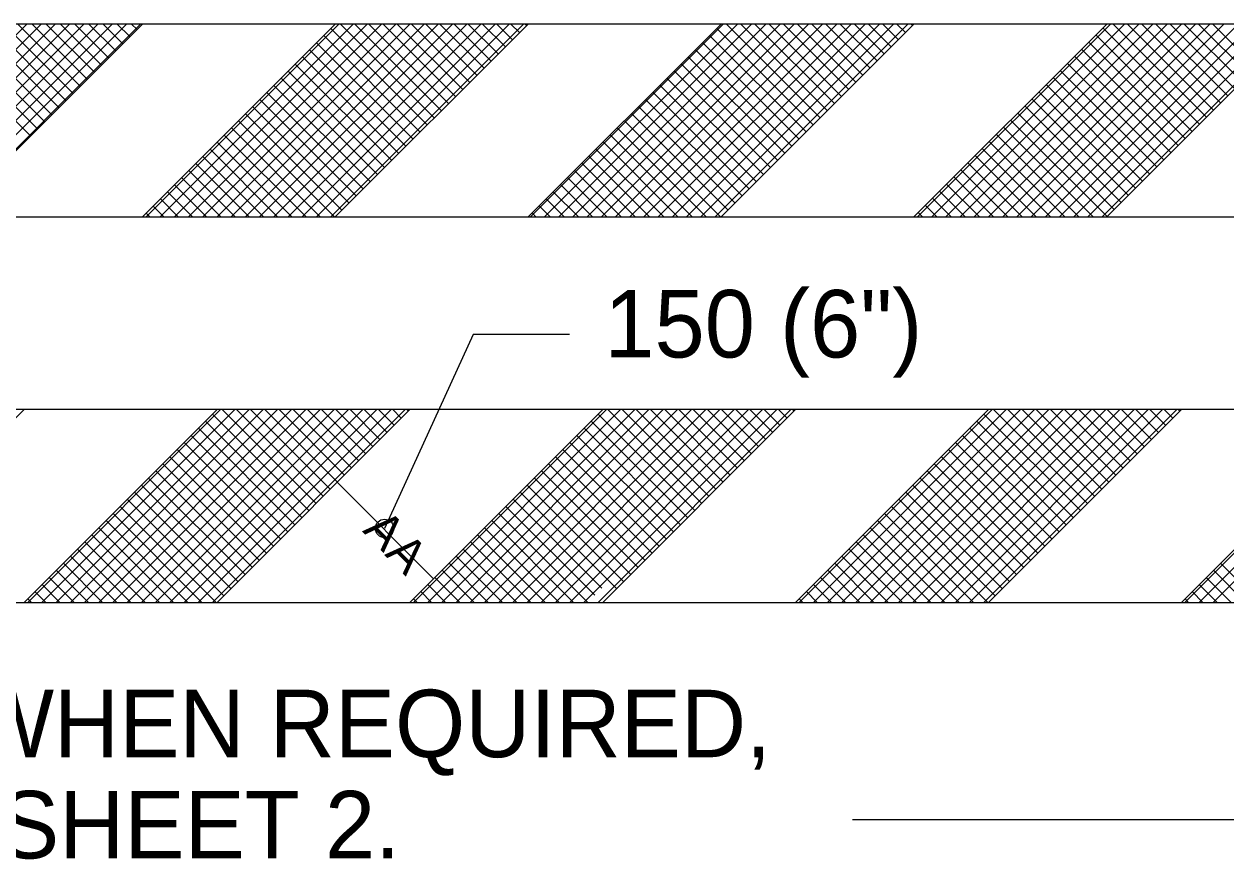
# Model space of a CAD drawing. Extents: x -4 to 901, y -468 to 720.
# Drawn here: x 457.6 to 517.4, y 595.4 to 637.6 of the extents above; entities that cross this region are included whole.
import ezdxf

# ---------------------------------------------------------------- set-up
doc = ezdxf.new("R2010")
doc.units = 0
doc.layers.add('2', color=7, linetype='Continuous')
doc.layers.add('3', color=7, linetype='Continuous')

msp = doc.modelspace()

# ---------------------------------------------------------------- linework, layer by layer
at = {"layer": '2'}
for p, q in [((453.8525, 627.995125), (463.4525, 637.595125)), ((463.4525, 627.995125), (473.0525, 637.595125)), ((473.0525, 627.995125), (482.6525, 637.595125)), ((482.6525, 627.995125), (492.2525, 637.595125)), ((492.2525, 627.995125), (501.8525, 637.595125)), ((501.8525, 627.995125), (511.4525, 637.595125)), ((511.4525, 627.995125), (521.0525, 637.595125)), ((447.9665, 608.795125), (457.5665, 618.395125)), ((457.5665, 608.795125), (467.1665, 618.395125)), ((457.5665, 608.795125), (467.1665, 618.395125)), ((457.5665, 608.795125), (467.1665, 618.395125)), ((457.5665, 608.795125), (467.1665, 618.395125)), ((457.5665, 608.795125), (467.1665, 618.395125)), ((462.7045, 613.933125), (467.1665, 618.395125)), ((467.1665, 608.795125), (476.7665, 618.395125)), ((476.7665, 608.795125), (486.3665, 618.395125)), ((476.7665, 608.795125), (486.3665, 618.395125)), ((476.7665, 608.795125), (486.3665, 618.395125)), ((476.7665, 608.795125), (486.3665, 618.395125)), ((476.7665, 608.795125), (486.3665, 618.395125)), ((476.7665, 608.795125), (486.3665, 618.395125)), ((481.9045, 613.933125), (486.3665, 618.395125)), ((486.3665, 608.795125), (495.9665, 618.395125)), ((495.9665, 608.795125), (505.5665, 618.395125)), ((495.9665, 608.795125), (505.5665, 618.395125)), ((495.9665, 608.795125), (505.5665, 618.395125)), ((495.9665, 608.795125), (505.5665, 618.395125)), ((495.9665, 608.795125), (505.5665, 618.395125)), ((495.9665, 608.795125), (505.5665, 618.395125)), ((495.9665, 608.795125), (505.5665, 618.395125)), ((501.1045, 613.933125), (505.5665, 618.395125)), ((505.5665, 608.795125), (515.1665, 618.395125)), ((515.1665, 608.795125), (524.7665, 618.395125)), ((515.1665, 608.795125), (524.7665, 618.395125)), ((515.1665, 608.795125), (524.7665, 618.395125)), ((515.1665, 608.795125), (524.7665, 618.395125)), ((515.1665, 608.795125), (524.7665, 618.395125)), ((515.1665, 608.795125), (524.7665, 618.395125)), ((515.1665, 608.795125), (524.7665, 618.395125)), ((515.1665, 608.795125), (524.7665, 618.395125)), ((477.9465, 609.975125), (473.1465, 614.775125)), ((519.64075, 597.967625), (498.79225, 597.967625))]:
    msp.add_line(p, q, dxfattribs=at)
for points in [[(405.1045, 637.595125), (405.1045, 627.995125), (536.7925, 627.995125), (536.7925, 637.595125)], [(405.1045, 618.395125), (405.1045, 608.795125), (536.7925, 608.795125), (536.7925, 618.395125)]]:
    msp.add_lwpolyline(points, close=True, dxfattribs=at)
for points in [[(448.1, 627.995125), (457.7, 637.595125)], [(448.807, 627.995125), (458.407, 637.595125)], [(449.514, 627.995125), (459.114, 637.595125)], [(450.2215, 627.995125), (459.8215, 637.595125)], [(450.9285, 627.995125), (460.5285, 637.595125)], [(451.6355, 627.995125), (461.2355, 637.595125)], [(452.3425, 627.995125), (461.9425, 637.595125)], [(453.05, 627.995125), (462.65, 637.595125)], [(453.757, 627.995125), (463.357, 637.595125)], [(458.584, 632.726625), (453.784, 637.526625)], [(458.9375, 633.080125), (454.4225, 637.595125)], [(459.291, 633.433625), (455.1295, 637.595125)], [(459.6445, 633.787125), (455.8365, 637.595125)], [(459.998, 634.140625), (456.5435, 637.595125)], [(460.35175, 634.494375), (457.251, 637.595125)], [(460.70525, 634.847875), (457.958, 637.595125)], [(461.05875, 635.201375), (458.665, 637.595125)], [(461.41225, 635.554875), (459.372, 637.595125)], [(461.76575, 635.908375), (460.079, 637.595125)], [(462.1195, 636.262125), (460.7865, 637.595125)], [(462.473, 636.615625), (461.4935, 637.595125)], [(462.8265, 636.969125), (462.2005, 637.595125)], [(463.18, 637.322625), (462.9075, 637.595125)], [(463.62875, 627.995125), (473.22875, 637.595125)], [(464.33575, 627.995125), (473.93575, 637.595125)], [(465.04275, 627.995125), (474.64275, 637.595125)], [(465.74975, 627.995125), (475.34975, 637.595125)], [(466.45675, 627.995125), (476.05675, 637.595125)], [(467.16375, 627.995125), (476.76375, 637.595125)], [(467.87075, 627.995125), (477.47075, 637.595125)], [(468.57825, 627.995125), (478.17825, 637.595125)], [(469.28525, 627.995125), (478.88525, 637.595125)], [(469.99225, 627.995125), (479.59225, 637.595125)], [(470.69925, 627.995125), (480.29925, 637.595125)], [(471.40675, 627.995125), (481.00675, 637.595125)], [(472.11375, 627.995125), (481.71375, 637.595125)], [(472.82075, 627.995125), (482.42075, 637.595125)], [(477.62675, 632.569625), (472.827, 637.369375)], [(477.98025, 632.923125), (473.30825, 637.595125)], [(478.33375, 633.276625), (474.01525, 637.595125)], [(478.68725, 633.630125), (474.72225, 637.595125)], [(479.04075, 633.983625), (475.42925, 637.595125)], [(479.3945, 634.337375), (476.13675, 637.595125)], [(479.748, 634.690875), (476.84375, 637.595125)], [(480.1015, 635.044375), (477.55075, 637.595125)], [(480.455, 635.397875), (478.25775, 637.595125)], [(480.8085, 635.751375), (478.96475, 637.595125)], [(481.162, 636.104875), (479.67175, 637.595125)], [(481.5155, 636.458375), (480.37875, 637.595125)], [(481.869, 636.811875), (481.08575, 637.595125)], [(482.2225, 637.165375), (481.79275, 637.595125)], [(482.57625, 637.519125), (482.50025, 637.595125)], [(482.76, 627.995125), (492.36, 637.595125)], [(483.467, 627.995125), (493.067, 637.595125)], [(484.1745, 627.995125), (493.7745, 637.595125)], [(484.8815, 627.995125), (494.4815, 637.595125)], [(485.5885, 627.995125), (495.1885, 637.595125)], [(486.2955, 627.995125), (495.8955, 637.595125)], [(487.003, 627.995125), (496.603, 637.595125)], [(487.71, 627.995125), (497.31, 637.595125)], [(488.417, 627.995125), (498.017, 637.595125)], [(489.124, 627.995125), (498.724, 637.595125)], [(489.831, 627.995125), (499.431, 637.595125)], [(490.5385, 627.995125), (500.1385, 637.595125)], [(491.2455, 627.995125), (500.8455, 637.595125)], [(491.9525, 627.995125), (501.5525, 637.595125)], [(496.8355, 632.578125), (492.0355, 637.378125)], [(497.189, 632.931625), (492.5255, 637.595125)], [(497.5425, 633.285125), (493.2325, 637.595125)], [(497.896, 633.638625), (493.9395, 637.595125)], [(498.24975, 633.992375), (494.647, 637.595125)], [(498.60325, 634.345875), (495.354, 637.595125)], [(498.95675, 634.699375), (496.061, 637.595125)], [(499.31025, 635.052875), (496.768, 637.595125)], [(499.66375, 635.406375), (497.475, 637.595125)], [(500.0175, 635.760125), (498.1825, 637.595125)], [(500.371, 636.113625), (498.8895, 637.595125)], [(500.7245, 636.467125), (499.5965, 637.595125)], [(501.078, 636.820625), (500.3035, 637.595125)], [(501.43175, 637.174375), (501.011, 637.595125)], [(501.78525, 637.527875), (501.718, 637.595125)], [(502.032, 627.995125), (511.632, 637.595125)], [(502.739, 627.995125), (512.339, 637.595125)], [(503.4465, 627.995125), (513.0465, 637.595125)], [(504.1535, 627.995125), (513.7535, 637.595125)], [(504.8605, 627.995125), (514.4605, 637.595125)], [(505.5675, 627.995125), (515.1675, 637.595125)], [(506.275, 627.995125), (515.875, 637.595125)], [(506.982, 627.995125), (516.582, 637.595125)], [(507.689, 627.995125), (517.289, 637.595125)], [(508.396, 627.995125), (517.996, 637.595125)], [(509.103, 627.995125), (518.703, 637.595125)], [(509.8105, 627.995125), (519.4105, 637.595125)], [(510.5175, 627.995125), (520.1175, 637.595125)], [(511.2245, 627.995125), (520.8245, 637.595125)], [(516.06225, 632.605125), (511.26225, 637.405125)], [(516.41575, 632.958625), (511.77925, 637.595125)], [(516.76925, 633.312125), (512.48625, 637.595125)], [(517.12275, 633.665625), (513.19325, 637.595125)], [(517.4765, 634.019375), (513.90075, 637.595125)], [(517.83, 634.372875), (514.60775, 637.595125)], [(518.1835, 634.726375), (515.31475, 637.595125)], [(518.537, 635.079875), (516.02175, 637.595125)], [(518.8905, 635.433375), (516.72875, 637.595125)], [(457.87675, 632.019375), (453.07675, 636.819375)], [(458.23025, 632.372875), (453.43025, 637.172875)], [(476.9195, 631.861875), (472.1195, 636.661875)], [(477.27325, 632.215625), (472.47325, 637.015625)], [(496.12825, 631.870875), (491.32825, 636.670875)], [(496.482, 632.224625), (491.682, 637.024625)], [(515.355, 631.897875), (510.555, 636.697875)], [(515.70875, 632.251625), (510.90875, 637.051625)], [(476.566, 631.508375), (471.766, 636.308375)], [(495.77475, 631.517375), (490.97475, 636.317375)], [(515.0015, 631.544375), (510.2015, 636.344375)], [(475.859, 630.801375), (471.059, 635.601375)], [(476.2125, 631.154875), (471.4125, 635.954875)], [(495.06775, 630.810375), (490.26775, 635.610375)], [(495.42125, 631.163875), (490.62125, 635.963875)], [(514.2945, 630.837375), (509.4945, 635.637375)], [(514.648, 631.190875), (509.848, 635.990875)], [(475.15175, 630.094125), (470.35175, 634.894125)], [(475.50525, 630.447625), (470.70525, 635.247625)], [(494.3605, 630.103125), (489.5605, 634.903125)], [(494.714, 630.456625), (489.914, 635.256625)], [(513.58725, 630.130125), (508.78725, 634.930125)], [(513.94075, 630.483625), (509.14075, 635.283625)], [(474.79825, 629.740625), (469.99825, 634.540625)], [(494.007, 629.749625), (489.207, 634.549625)], [(512.88025, 629.423125), (508.08025, 634.223125)], [(513.23375, 629.776625), (508.43375, 634.576625)], [(474.09125, 629.033625), (469.29125, 633.833625)], [(474.44475, 629.387125), (469.64475, 634.187125)], [(493.3, 629.042625), (488.5, 633.842625)], [(493.6535, 629.396125), (488.8535, 634.196125)], [(512.52675, 629.069625), (507.72675, 633.869625)], [(473.384, 628.326375), (468.584, 633.126375)], [(473.7375, 628.679875), (468.9375, 633.479875)], [(492.59275, 628.335375), (487.79275, 633.135375)], [(492.94625, 628.688875), (488.14625, 633.488875)], [(511.8195, 628.362375), (507.0195, 633.162375)], [(512.173, 628.715875), (507.373, 633.515875)], [(472.30125, 627.995125), (467.877, 632.419375)], [(473.0305, 627.972875), (468.2305, 632.772875)], [(491.519, 627.995125), (487.08575, 632.428375)], [(492.23925, 627.981875), (487.43925, 632.781875)], [(510.77275, 627.995125), (506.3125, 632.455375)], [(511.466, 628.008875), (506.666, 632.808875)], [(471.59425, 627.995125), (467.5235, 632.065875)], [(490.812, 627.995125), (486.73225, 632.074875)], [(510.06575, 627.995125), (505.959, 632.101875)], [(470.18025, 627.995125), (466.8165, 631.358875)], [(470.88725, 627.995125), (467.17, 631.712375)], [(489.3975, 627.995125), (486.025, 631.367625)], [(490.1045, 627.995125), (486.3785, 631.721125)], [(508.65125, 627.995125), (505.25175, 631.394625)], [(509.35825, 627.995125), (505.60525, 631.748125)], [(468.76625, 627.995125), (466.1095, 630.651875)], [(469.47325, 627.995125), (466.463, 631.005375)], [(487.9835, 627.995125), (485.318, 630.660625)], [(488.6905, 627.995125), (485.6715, 631.014125)], [(507.23725, 627.995125), (504.54475, 630.687625)], [(507.94425, 627.995125), (504.89825, 631.041125)], [(468.05875, 627.995125), (465.75575, 630.298125)], [(487.2765, 627.995125), (484.9645, 630.307125)], [(506.53025, 627.995125), (504.19125, 630.334125)], [(466.64475, 627.995125), (465.04875, 629.591125)], [(467.35175, 627.995125), (465.40225, 629.944625)], [(485.862, 627.995125), (484.25725, 629.599875)], [(486.569, 627.995125), (484.61075, 629.953375)], [(505.11575, 627.995125), (503.484, 629.626875)], [(505.82275, 627.995125), (503.8375, 629.980375)], [(465.23075, 627.995125), (464.34175, 628.884125)], [(465.93775, 627.995125), (464.69525, 629.237625)], [(484.448, 627.995125), (483.55025, 628.892875)], [(485.155, 627.995125), (483.90375, 629.246375)], [(503.70175, 627.995125), (502.777, 628.919875)], [(504.40875, 627.995125), (503.1305, 629.273375)], [(464.52325, 627.995125), (463.988, 628.530375)], [(483.7405, 627.995125), (483.1965, 628.539125)], [(502.99425, 627.995125), (502.42325, 628.566125)], [(463.81625, 627.995125), (463.6345, 628.176875)], [(483.0335, 627.995125), (482.843, 628.185625)], [(502.28725, 627.995125), (502.06975, 628.212625)], [(484.7145, 622.141125), (479.9145, 622.141125), (475.5025, 612.477125)], [(457.74275, 608.795125), (467.34275, 618.395125)], [(458.44975, 608.795125), (468.04975, 618.395125)], [(459.15675, 608.795125), (468.75675, 618.395125)], [(459.86375, 608.795125), (469.46375, 618.395125)], [(460.57075, 608.795125), (470.17075, 618.395125)], [(461.27775, 608.795125), (470.87775, 618.395125)], [(461.98475, 608.795125), (471.58475, 618.395125)], [(462.69225, 608.795125), (472.29225, 618.395125)], [(463.39925, 608.795125), (472.99925, 618.395125)], [(464.10625, 608.795125), (473.70625, 618.395125)], [(464.81325, 608.795125), (474.41325, 618.395125)], [(465.52075, 608.795125), (475.12075, 618.395125)], [(466.22775, 608.795125), (475.82775, 618.395125)], [(466.93475, 608.795125), (476.53475, 618.395125)], [(471.7405, 613.369375), (466.94075, 618.169125)], [(472.094, 613.722875), (467.42175, 618.395125)], [(472.4475, 614.076375), (468.12875, 618.395125)], [(472.801, 614.429875), (468.83575, 618.395125)], [(473.1545, 614.783375), (469.54275, 618.395125)], [(473.50825, 615.137125), (470.25025, 618.395125)], [(473.86175, 615.490625), (470.95725, 618.395125)], [(474.2155, 615.844375), (471.66475, 618.395125)], [(474.569, 616.197875), (472.37175, 618.395125)], [(474.9225, 616.551375), (473.07875, 618.395125)], [(475.276, 616.904875), (473.78575, 618.395125)], [(475.6295, 617.258375), (474.49275, 618.395125)], [(475.983, 617.611875), (475.19975, 618.395125)], [(476.3365, 617.965375), (475.90675, 618.395125)], [(476.69025, 618.319125), (476.61425, 618.395125)], [(476.94275, 608.795125), (486.54275, 618.395125)], [(477.64975, 608.795125), (487.24975, 618.395125)], [(478.35675, 608.795125), (487.95675, 618.395125)], [(479.06375, 608.795125), (488.66375, 618.395125)], [(479.77075, 608.795125), (489.37075, 618.395125)], [(480.47775, 608.795125), (490.07775, 618.395125)], [(481.18475, 608.795125), (490.78475, 618.395125)], [(481.89225, 608.795125), (491.49225, 618.395125)], [(482.59925, 608.795125), (492.19925, 618.395125)], [(483.30625, 608.795125), (492.90625, 618.395125)], [(484.01325, 608.795125), (493.61325, 618.395125)], [(484.72075, 608.795125), (494.32075, 618.395125)], [(485.42775, 608.795125), (495.02775, 618.395125)], [(486.13475, 608.795125), (495.73475, 618.395125)], [(490.9405, 613.369375), (486.14075, 618.169125)], [(491.294, 613.722875), (486.62175, 618.395125)], [(491.6475, 614.076375), (487.32875, 618.395125)], [(492.001, 614.429875), (488.03575, 618.395125)], [(492.3545, 614.783375), (488.74275, 618.395125)], [(492.70825, 615.137125), (489.45025, 618.395125)], [(493.06175, 615.490625), (490.15725, 618.395125)], [(493.4155, 615.844375), (490.86475, 618.395125)], [(493.769, 616.197875), (491.57175, 618.395125)], [(494.1225, 616.551375), (492.27875, 618.395125)], [(494.476, 616.904875), (492.98575, 618.395125)], [(494.8295, 617.258375), (493.69275, 618.395125)], [(495.183, 617.611875), (494.39975, 618.395125)], [(495.5365, 617.965375), (495.10675, 618.395125)], [(495.89025, 618.319125), (495.81425, 618.395125)], [(496.14275, 608.795125), (505.74275, 618.395125)], [(496.84975, 608.795125), (506.44975, 618.395125)], [(497.55675, 608.795125), (507.15675, 618.395125)], [(498.26375, 608.795125), (507.86375, 618.395125)], [(498.97075, 608.795125), (508.57075, 618.395125)], [(499.67775, 608.795125), (509.27775, 618.395125)], [(500.38475, 608.795125), (509.98475, 618.395125)], [(501.09225, 608.795125), (510.69225, 618.395125)], [(501.79925, 608.795125), (511.39925, 618.395125)], [(502.50625, 608.795125), (512.10625, 618.395125)], [(503.21325, 608.795125), (512.81325, 618.395125)], [(503.92075, 608.795125), (513.52075, 618.395125)], [(504.62775, 608.795125), (514.22775, 618.395125)], [(505.33475, 608.795125), (514.93475, 618.395125)], [(510.1405, 613.369375), (505.34075, 618.169125)], [(510.494, 613.722875), (505.82175, 618.395125)], [(510.8475, 614.076375), (506.52875, 618.395125)], [(511.201, 614.429875), (507.23575, 618.395125)], [(511.5545, 614.783375), (507.94275, 618.395125)], [(511.90825, 615.137125), (508.65025, 618.395125)], [(512.26175, 615.490625), (509.35725, 618.395125)], [(512.6155, 615.844375), (510.06475, 618.395125)], [(512.969, 616.197875), (510.77175, 618.395125)], [(513.3225, 616.551375), (511.47875, 618.395125)], [(513.676, 616.904875), (512.18575, 618.395125)], [(514.0295, 617.258375), (512.89275, 618.395125)], [(514.383, 617.611875), (513.59975, 618.395125)], [(514.7365, 617.965375), (514.30675, 618.395125)], [(515.09025, 618.319125), (515.01425, 618.395125)], [(515.34275, 608.795125), (524.94275, 618.395125)], [(516.04975, 608.795125), (525.64975, 618.395125)], [(516.75675, 608.795125), (526.35675, 618.395125)], [(471.0335, 612.662375), (466.23375, 617.462125)], [(471.387, 613.015875), (466.58725, 617.815625)], [(490.2335, 612.662375), (485.43375, 617.462125)], [(490.587, 613.015875), (485.78725, 617.815625)], [(509.4335, 612.662375), (504.63375, 617.462125)], [(509.787, 613.015875), (504.98725, 617.815625)], [(470.68, 612.308875), (465.88025, 617.108625)], [(489.87975, 612.308625), (485.08, 617.108375)], [(509.07975, 612.308625), (504.28, 617.108375)], [(469.97275, 611.601625), (465.173, 616.401375)], [(470.3265, 611.955375), (465.52675, 616.755125)], [(489.1725, 611.601375), (484.37275, 616.401125)], [(489.52625, 611.955125), (484.7265, 616.754875)], [(508.3725, 611.601375), (503.57275, 616.401125)], [(508.72625, 611.955125), (503.9265, 616.754875)], [(469.2655, 610.894375), (464.46575, 615.694125)], [(469.61925, 611.248125), (464.8195, 616.047875)], [(488.4655, 610.894375), (483.66575, 615.694125)], [(488.819, 611.247875), (484.01925, 616.047625)], [(507.6655, 610.894375), (502.86575, 615.694125)], [(508.019, 611.247875), (503.21925, 616.047625)], [(468.912, 610.540875), (464.11225, 615.340625)], [(488.112, 610.540875), (483.31225, 615.340625)], [(507.312, 610.540875), (502.51225, 615.340625)], [(468.205, 609.833875), (463.40525, 614.633625)], [(468.5585, 610.187375), (463.75875, 614.987125)], [(487.405, 609.833875), (482.60525, 614.633625)], [(487.7585, 610.187375), (482.95875, 614.987125)], [(506.605, 609.833875), (501.80525, 614.633625)], [(506.9585, 610.187375), (502.15875, 614.987125)], [(467.498, 609.126875), (462.69825, 613.926625)], [(467.8515, 609.480375), (463.05175, 614.280125)], [(486.32225, 609.502125), (481.898, 613.926375)], [(487.0515, 609.480375), (482.25175, 614.280125)], [(505.898, 609.126875), (501.09825, 613.926625)], [(506.2515, 609.480375), (501.45175, 614.280125)], [(467.1445, 608.773375), (462.34475, 613.573125)], [(485.96875, 609.148625), (481.5445, 613.572875)], [(505.5445, 608.773375), (500.74475, 613.573125)], [(465.70825, 608.795125), (461.6375, 612.865875)], [(466.41525, 608.795125), (461.991, 613.219375)], [(484.90825, 608.795125), (480.8375, 612.865875)], [(485.61525, 608.795125), (481.191, 613.219375)], [(504.10825, 608.795125), (500.0375, 612.865875)], [(504.81525, 608.795125), (500.391, 613.219375)], [(464.29425, 608.795125), (460.9305, 612.158875)], [(465.00125, 608.795125), (461.284, 612.512375)], [(483.49425, 608.795125), (480.1305, 612.158875)], [(484.20125, 608.795125), (480.484, 612.512375)], [(502.69425, 608.795125), (499.3305, 612.158875)], [(503.40125, 608.795125), (499.684, 612.512375)], [(463.58725, 608.795125), (460.577, 611.805375)], [(482.78725, 608.795125), (479.777, 611.805375)], [(501.98725, 608.795125), (498.977, 611.805375)], [(462.17275, 608.795125), (459.86975, 611.098125)], [(462.88025, 608.795125), (460.2235, 611.451875)], [(481.37275, 608.795125), (479.06975, 611.098125)], [(482.08025, 608.795125), (479.4235, 611.451875)], [(500.57275, 608.795125), (498.26975, 611.098125)], [(501.28025, 608.795125), (498.6235, 611.451875)], [(460.75875, 608.795125), (459.16275, 610.391125)], [(461.46575, 608.795125), (459.51625, 610.744625)], [(479.95875, 608.795125), (478.36275, 610.391125)], [(480.66575, 608.795125), (478.71625, 610.744625)], [(499.15875, 608.795125), (497.56275, 610.391125)], [(499.86575, 608.795125), (497.91625, 610.744625)], [(518.35875, 608.795125), (516.76275, 610.391125)], [(519.06575, 608.795125), (517.11625, 610.744625)], [(459.34475, 608.795125), (458.45575, 609.684125)], [(460.05175, 608.795125), (458.80925, 610.037625)], [(478.54475, 608.795125), (477.65575, 609.684125)], [(479.25175, 608.795125), (478.00925, 610.037625)], [(497.74475, 608.795125), (496.85575, 609.684125)], [(498.45175, 608.795125), (497.20925, 610.037625)], [(516.94475, 608.795125), (516.05575, 609.684125)], [(517.65175, 608.795125), (516.40925, 610.037625)], [(458.63725, 608.795125), (458.102, 609.330375)], [(477.83725, 608.795125), (477.302, 609.330375)], [(497.03725, 608.795125), (496.502, 609.330375)], [(516.23725, 608.795125), (515.702, 609.330375)], [(457.93025, 608.795125), (457.7485, 608.976875)], [(477.13025, 608.795125), (476.9485, 608.976875)], [(496.33025, 608.795125), (496.1485, 608.976875)], [(515.53025, 608.795125), (515.3485, 608.976875)]]:
    msp.add_lwpolyline(points, dxfattribs=at)
msp.add_circle((475.50251, 612.477232), 0.455664, dxfattribs=at)

# ---------------------------------------------------------------- texts
for p in [(474.3685, 612.331125), (475.47475, 611.162625)]:
    msp.add_text('A', height=1.727988, rotation=315.00375278, dxfattribs=at).set_placement(p)
at = {"layer": '3'}
for s, height, p in [('150 (6")', 3.36, (486.44225, 620.989875)), ('BUTT SPLICE, WHEN REQUIRED,', 3.359988, (423.3495, 601.084125)), ('SEE DETAIL D, SHEET 2.', 3.359988, (423.3495, 596.044125))]:
    msp.add_text(s, height=height, dxfattribs=at).set_placement(p)

doc.saveas('drawing.dxf')
